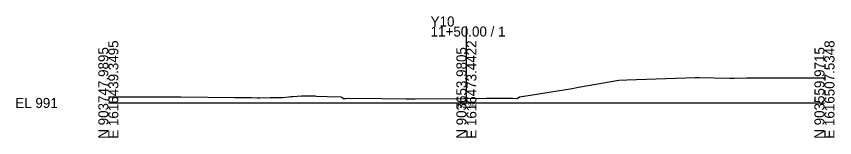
# Model space of a CAD drawing. Extents: x -26 to 203, y -10 to 3046.
# Drawn here: x -25.7 to 202.8, y 1490.3 to 1524.2 of the extents above; entities that cross this region are included whole.
import ezdxf

# ---------------------------------------------------------------- set-up
doc = ezdxf.new("R2010")
doc.units = 0
for name, color, linetype in [('Exist Cross Section Cell', 7, 'Continuous'), ('Exist XS Center Line Elevation Label', 7, 'Continuous'), ('Exist XS Ground Line', 7, 'Continuous')]:
    doc.layers.add(name, color=color, linetype=linetype)

msp = doc.modelspace()

# ---------------------------------------------------------------- linework, layer by layer
at = {"layer": 'Exist Cross Section Cell'}
for p, q in [((100, 1500), (100, 1521.37)), ((0, 1500), (100, 1500)), ((100, 1500), (200, 1500))]:
    msp.add_line(p, q, dxfattribs=at)
at = {"layer": 'Exist XS Ground Line'}
for p, q in [((131.33, 1504.41), (142.55, 1506.39)), ((142.55, 1506.39), (144.78, 1506.46)), ((144.78, 1506.46), (163.9, 1507.12)), ((163.9, 1507.12), (164.97, 1507.09)), ((164.97, 1507.09), (169.33, 1506.99)), ((169.33, 1506.99), (173.53, 1506.92)), ((173.53, 1506.92), (174.84, 1506.94)), ((174.84, 1506.94), (178.23, 1506.99)), ((178.23, 1506.99), (178.9, 1507)), ((178.9, 1507), (181.06, 1507.04)), ((181.06, 1507.04), (182.12, 1507.03)), ((182.12, 1507.03), (183.53, 1507.04)), ((183.53, 1507.04), (185.79, 1507.03)), ((185.79, 1507.03), (188.3, 1507.05)), ((188.3, 1507.05), (190.58, 1507.05)), ((190.58, 1507.05), (194.46, 1507.06)), ((194.46, 1507.06), (197.32, 1507.05)), ((197.32, 1507.05), (200, 1507.04)), ((119.01, 1502.34), (129.51, 1504.09)), ((129.51, 1504.09), (131.33, 1504.41)), ((0, 1501.75), (8.13, 1501.73)), ((8.13, 1501.73), (20.23, 1501.75)), ((20.23, 1501.75), (35.22, 1501.5)), ((35.22, 1501.5), (38.14, 1501.5)), ((38.14, 1501.5), (39.99, 1501.5)), ((39.99, 1501.5), (41.52, 1501.48)), ((41.52, 1501.48), (41.82, 1501.47)), ((41.82, 1501.47), (42.29, 1501.46)), ((42.29, 1501.46), (45.17, 1501.49)), ((45.17, 1501.49), (48.66, 1501.52)), ((48.66, 1501.52), (50.37, 1501.74)), ((50.37, 1501.74), (50.99, 1501.82)), ((50.99, 1501.82), (51.54, 1501.84)), ((51.54, 1501.84), (53.95, 1501.97)), ((53.95, 1501.97), (55.19, 1501.97)), ((55.19, 1501.97), (56.59, 1502.01)), ((56.59, 1502.01), (57.73, 1501.97)), ((57.73, 1501.97), (58.12, 1501.93)), ((58.12, 1501.93), (61.13, 1501.85)), ((61.13, 1501.85), (64.94, 1501.75)), ((64.94, 1501.75), (65.3, 1501.51)), ((65.3, 1501.51), (65.67, 1501.27)), ((114.17, 1501.28), (114.85, 1501.73)), ((114.85, 1501.73), (119.01, 1502.34)), ((65.67, 1501.27), (66.3, 1501.28)), ((66.3, 1501.28), (66.95, 1501.3)), ((66.95, 1501.3), (76.39, 1501.21)), ((76.39, 1501.21), (83.18, 1501.16)), ((83.18, 1501.16), (85.73, 1501.18)), ((85.73, 1501.18), (99.37, 1501.25)), ((99.37, 1501.25), (100, 1501.26)), ((100, 1501.26), (105.51, 1501.3)), ((105.51, 1501.3), (113.01, 1501.33)), ((113.01, 1501.33), (114.17, 1501.28))]:
    msp.add_line(p, q, dxfattribs=at)

# ---------------------------------------------------------------- texts
at = {"layer": 'Exist Cross Section Cell'}
for s, p in [('Y10', (90, 1521.37)), ('11+50.00 / 1', (90, 1518.57)), ('EL 991', (-26, 1498.6))]:
    msp.add_text(s, height=2.8, dxfattribs=at).set_placement(p)
for s, p in [('N 903747.9895', (0, 1490)), ('E 1616439.3495', (2.8, 1490)), ('N 903653.9805', (100, 1490)), ('E 1616473.4422', (102.8, 1490)), ('N 903559.9715', (200, 1490)), ('E 1616507.5348', (202.8, 1490))]:
    msp.add_text(s, height=2.8, rotation=90, dxfattribs=at).set_placement(p)
at = {"layer": 'Exist XS Center Line Elevation Label'}
msp.add_text('992.26', height=1.25, dxfattribs=at).set_placement((97.07, 1498.63))

doc.saveas('drawing.dxf')
